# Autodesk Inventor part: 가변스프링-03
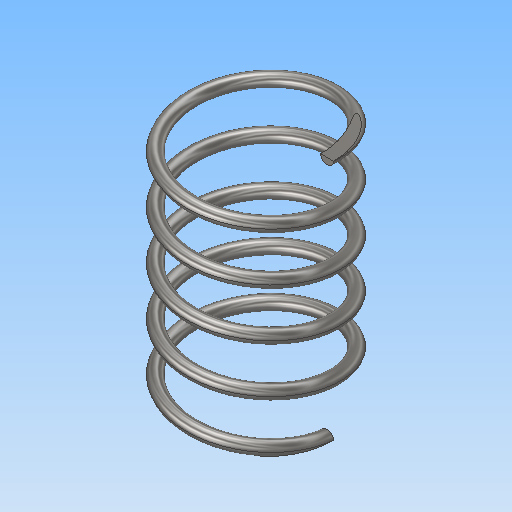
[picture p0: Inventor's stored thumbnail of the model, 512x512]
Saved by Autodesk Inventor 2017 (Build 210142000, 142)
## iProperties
Part Number: 가변스프링-03
Material: 강철, 연강
Document SubType Name: Modeling
Designer: MRC
Density: 7.85 g/cm^3
Appearance: 반연마
Mass: 8.4237 g
Surface Area: 21.7266 cm^2
Volume: 1.07308 cm^3
Author: MRC
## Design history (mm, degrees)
sketch "스케치1"
  geometry: L1 (0, 0)-(0, 37.411); L2 (0, 0)-(11, 0); L3 (0, 37.411)-(11, 37.411); C1 r 1 at (11, 0)
  constraints: 6 end point, 2 horizontal, 1 centre point, 1 coincident, 1 vertical
  dimensions: "d0" = 37.4112 distance of L1.start L1.end (derived); "d1" = 22 diameter of L2.end L1; "d2" = 2 diameter of C1; "d3" = 11 distance of L1.end L3.end
feature "코일1" sketch "스케치1" pitch "d4" = 10; turns "d6" = 5; dims "d5" = 37.4112 (= d0), "d7" = 0, angle "d8" = 90 deg, angle "d9" = 90 deg, "d10" = 0, "d11" = 0
sketch "스케치2"
  geometry: L1 (37.411, 12.5)-(0, 12.5); L2 (0, 12.5)-(0, -12.5); L3 (0, -12.5)-(37.411, -12.5); L4 (37.411, -12.5)-(37.411, 12.5); 2 further points
  constraints: 8 end point, 2 parallel, 1 coincident, 1 horizontal, 1 midpoint, 1 perpendicular
  dimensions: "d12" = 37.4112 distance of L2.end L3.end (= d0); "d13" = 25 distance of L3.end L1.start
extrude "돌출1" sketch "스케치2" stored distance "d14" = 0; taper "d15" = 0 deg
node "솔리드1"
